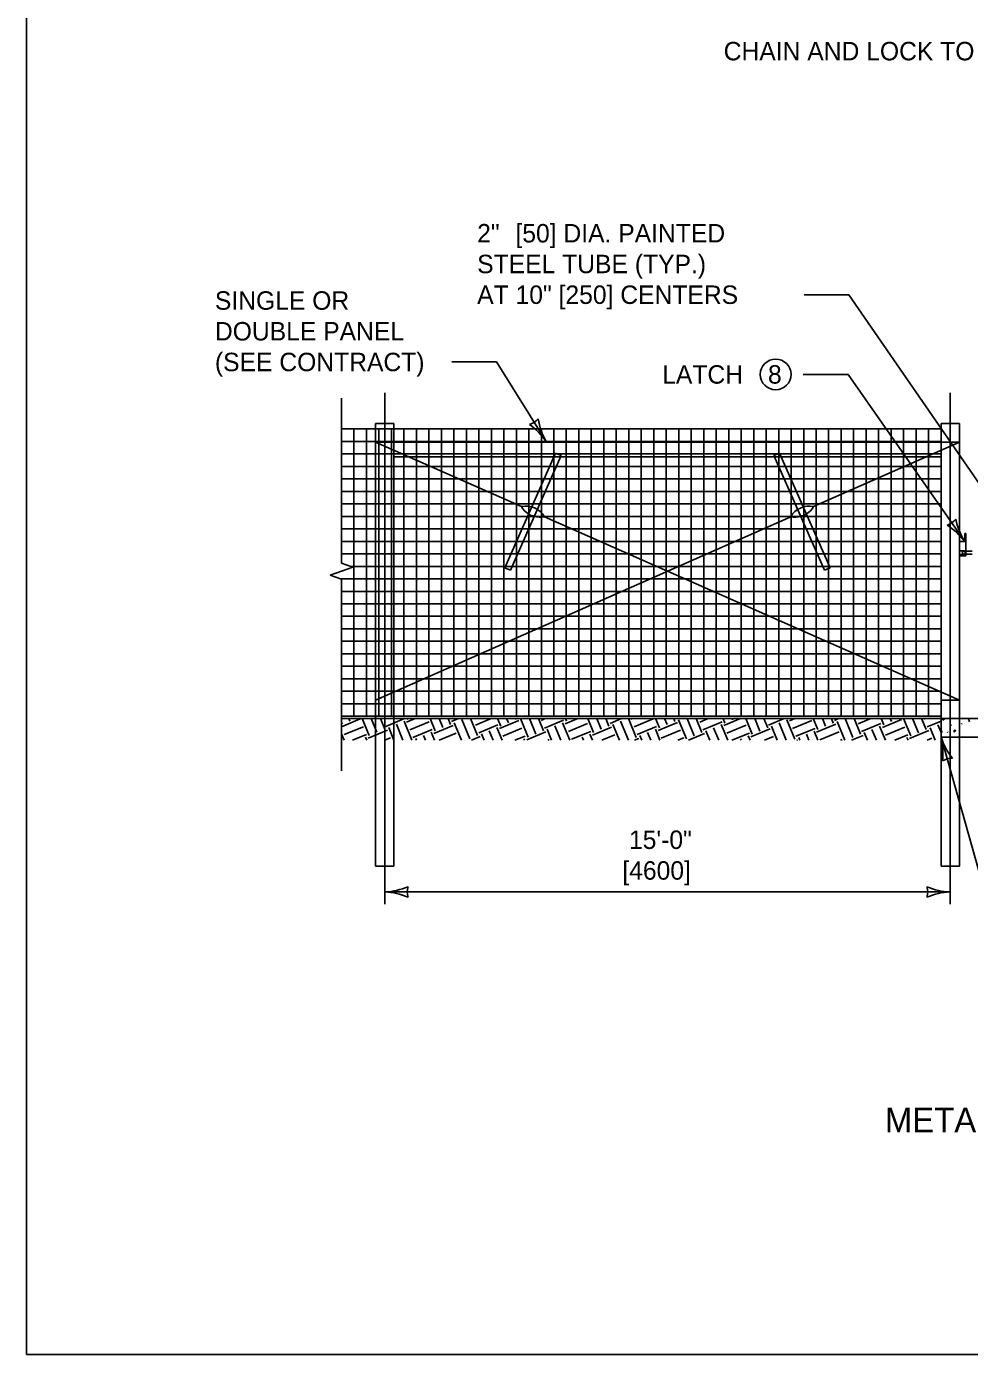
# Model space of a CAD drawing. Extents: x 49991.4 to 50021, y 49987.6 to 50011.4.
# Drawn here: x 49999.384 to 50002.451, y 49987.799 to 49992.12 of the extents above; entities that cross this region are included whole.
import ezdxf

# ---------------------------------------------------------------- set-up
doc = ezdxf.new("R2010")
doc.units = 0
for name, color, linetype in [('Level 1', 7, 'Continuous'), ('Level 2', 7, 'Continuous'), ('Level 3', 7, 'Continuous'), ('Level 4', 7, 'Continuous'), ('Level 5', 7, 'Continuous'), ('Level 6', 7, 'Continuous')]:
    doc.layers.add(name, color=color, linetype=linetype)

msp = doc.modelspace()

# ---------------------------------------------------------------- linework, layer by layer
at = {"layer": 'Level 1'}
for p, q in [((50000.5187, 49990.8278), (50000.5187, 49989.8678)), ((50000.5788, 49990.8278), (50000.5187, 49990.8278)), ((50000.5788, 49989.8678), (50000.5788, 49990.8278)), ((50002.3588, 49990.8278), (50002.3588, 49989.8078)), ((50002.4188, 49990.8278), (50002.3588, 49990.8278)), ((50002.4188, 49989.8678), (50002.4188, 49990.8278)), ((50002.3588, 49990.8105), (50000.4081, 49990.8105)), ((50000.4487, 49989.8757), (50000.4487, 49990.8105)), ((50000.4893, 49989.8757), (50000.4893, 49990.8105)), ((50000.5299, 49989.8757), (50000.5299, 49990.8105)), ((50000.5706, 49989.8757), (50000.5706, 49990.8105)), ((50000.6112, 49989.8757), (50000.6112, 49990.8105)), ((50000.6519, 49989.8757), (50000.6519, 49990.8105)), ((50000.6925, 49989.8757), (50000.6925, 49990.8105)), ((50000.7332, 49989.8757), (50000.7332, 49990.8105)), ((50000.7738, 49989.8757), (50000.7738, 49990.8105)), ((50000.8144, 49989.8757), (50000.8144, 49990.8105)), ((50000.8551, 49989.8757), (50000.8551, 49990.8105)), ((50000.8957, 49989.8757), (50000.8957, 49990.8105)), ((50000.9364, 49989.8757), (50000.9364, 49990.8105)), ((50000.977, 49989.8757), (50000.977, 49990.8105)), ((50001.0177, 49989.8757), (50001.0177, 49990.8105)), ((50001.0583, 49989.8757), (50001.0583, 49990.8105)), ((50001.0989, 49989.8757), (50001.0989, 49990.8105)), ((50001.1396, 49989.8757), (50001.1396, 49990.8105)), ((50001.1802, 49989.8757), (50001.1802, 49990.8105)), ((50001.2209, 49989.8757), (50001.2209, 49990.8105)), ((50001.2615, 49989.8757), (50001.2615, 49990.8105)), ((50001.3021, 49989.8757), (50001.3021, 49990.8105)), ((50001.3428, 49989.8757), (50001.3428, 49990.8105)), ((50001.3834, 49989.8757), (50001.3834, 49990.8105)), ((50001.4241, 49989.8757), (50001.4241, 49990.8105)), ((50001.4647, 49989.8757), (50001.4647, 49990.8105)), ((50001.5054, 49989.8757), (50001.5054, 49990.8105)), ((50001.546, 49989.8757), (50001.546, 49990.8105)), ((50001.5866, 49989.8757), (50001.5866, 49990.8105)), ((50001.6273, 49989.8757), (50001.6273, 49990.8105)), ((50001.6679, 49989.8757), (50001.6679, 49990.8105)), ((50001.7086, 49989.8757), (50001.7086, 49990.8105)), ((50001.7492, 49989.8757), (50001.7492, 49990.8105)), ((50001.7898, 49989.8757), (50001.7898, 49990.8105)), ((50001.8305, 49989.8757), (50001.8305, 49990.8105)), ((50001.8711, 49989.8757), (50001.8711, 49990.8105)), ((50001.9118, 49989.8757), (50001.9118, 49990.8105)), ((50001.9524, 49989.8757), (50001.9524, 49990.8105)), ((50001.9931, 49989.8757), (50001.9931, 49990.8105)), ((50002.0337, 49989.8757), (50002.0337, 49990.8105)), ((50002.0743, 49989.8757), (50002.0743, 49990.8105)), ((50002.115, 49989.8757), (50002.115, 49990.8105)), ((50002.1556, 49989.8757), (50002.1556, 49990.8105)), ((50002.1963, 49989.8757), (50002.1963, 49990.8105)), ((50002.2369, 49989.8757), (50002.2369, 49990.8105)), ((50002.2776, 49989.8757), (50002.2776, 49990.8105)), ((50002.3182, 49989.8757), (50002.3182, 49990.8105)), ((50002.3588, 49990.7698), (50000.4081, 49990.7698)), ((50002.3588, 49990.7292), (50000.4081, 49990.7292)), ((50000.5187, 49990.7678), (50002.4188, 49990.7678)), ((50000.5187, 49990.7678), (50000.9937, 49990.5578)), ((50000.9392, 49990.3586), (50001.1043, 49990.7321)), ((50001.1043, 49990.7321), (50001.1226, 49990.7241)), ((50001.8332, 49990.7322), (50001.8149, 49990.7241)), ((50001.9983, 49990.3586), (50001.8332, 49990.7322)), ((50002.4188, 49990.7678), (50001.9438, 49990.5577)), ((50002.3588, 49990.6885), (50000.4081, 49990.6885)), ((50000.5788, 49990.7198), (50002.3588, 49990.7198)), ((50001.1226, 49990.7241), (50000.9575, 49990.3505)), ((50001.8149, 49990.7241), (50001.98, 49990.3505)), ((50002.3588, 49990.6479), (50000.4081, 49990.6479)), ((50002.3588, 49990.6072), (50000.4081, 49990.6072)), ((50002.3588, 49990.5666), (50000.4081, 49990.5666)), ((50002.3588, 49990.526), (50000.4081, 49990.526)), ((50001.8695, 49990.5249), (50000.5187, 49989.9277)), ((50001.0681, 49990.5249), (50002.4188, 49989.9278)), ((50002.3588, 49990.4853), (50000.4081, 49990.4853)), ((50002.4363, 49990.4445), (50002.4363, 49990.4699)), ((50002.4363, 49990.4699), (50002.4389, 49990.4699)), ((50002.4389, 49990.4028), (50002.4389, 49990.4699)), ((50002.3588, 49990.4447), (50000.4081, 49990.4447)), ((50002.4189, 49990.4445), (50002.4389, 49990.4445)), ((50002.3588, 49990.404), (50000.4081, 49990.404)), ((50002.4188, 49990.414), (50002.4389, 49990.414)), ((50002.4188, 49990.4015), (50002.4389, 49990.4015)), ((50002.4188, 49990.3978), (50002.4389, 49990.3978)), ((50002.4289, 49990.4128), (50002.4289, 49990.4028)), ((50002.4289, 49990.4128), (50002.4376, 49990.4128)), ((50002.4289, 49990.4028), (50002.4376, 49990.4028)), ((50002.4376, 49990.4028), (50002.4376, 49990.414)), ((50002.4376, 49990.4028), (50002.4382, 49990.4022)), ((50002.4389, 49990.4028), (50002.4382, 49990.4022)), ((50002.4389, 49990.4128), (50002.4602, 49990.4128)), ((50002.4389, 49990.4028), (50002.4602, 49990.4028)), ((50002.4389, 49990.4015), (50002.4389, 49990.3978)), ((50002.3588, 49990.3634), (50000.4375, 49990.3634)), ((50000.9392, 49990.3586), (50000.9575, 49990.3505)), ((50001.9983, 49990.3586), (50001.98, 49990.3505)), ((50002.3588, 49990.3228), (50000.4057, 49990.3228)), ((50002.3588, 49990.2821), (50000.4081, 49990.2821)), ((50002.3588, 49990.2415), (50000.4081, 49990.2415)), ((50002.3588, 49990.2008), (50000.4081, 49990.2008)), ((50002.3588, 49990.1602), (50000.4081, 49990.1602)), ((50002.3588, 49990.1195), (50000.4081, 49990.1195)), ((50002.3588, 49990.0789), (50000.4081, 49990.0789)), ((50002.3588, 49990.0383), (50000.4081, 49990.0383)), ((50002.3588, 49989.9976), (50000.4081, 49989.9976)), ((50002.3588, 49989.957), (50000.4081, 49989.957)), ((50002.3588, 49989.9163), (50000.4081, 49989.9163)), ((50002.4188, 49989.9278), (50002.3588, 49989.9278)), ((50002.3588, 49989.8757), (50000.4081, 49989.8757)), ((50000.4081, 49989.8678), (50004.9435, 49989.8678)), ((50000.4081, 49989.8415), (50000.4689, 49989.8668)), ((50000.4324, 49989.8678), (50000.4357, 49989.8598)), ((50000.4759, 49989.8678), (50000.4986, 49989.813)), ((50000.5052, 49989.8678), (50000.5236, 49989.8234)), ((50000.5346, 49989.8678), (50000.5486, 49989.8337)), ((50000.5419, 49989.8677), (50000.5422, 49989.8678)), ((50000.5523, 49989.8426), (50000.6131, 49989.8678)), ((50000.6199, 49989.8565), (50000.6473, 49989.8678)), ((50000.6226, 49989.8678), (50000.6238, 49989.8649)), ((50000.6965, 49989.8678), (50000.7128, 49989.8284)), ((50000.7259, 49989.8678), (50000.7379, 49989.8388)), ((50000.7552, 49989.8678), (50000.7629, 49989.8491)), ((50000.7659, 49989.8582), (50000.789, 49989.8678)), ((50000.7999, 49989.8649), (50000.8258, 49989.8023)), ((50000.828, 49989.8678), (50000.8508, 49989.8127)), ((50000.8441, 49989.8466), (50000.8952, 49989.8678)), ((50000.9161, 49989.8678), (50000.926, 49989.8438)), ((50000.9454, 49989.8678), (50000.951, 49989.8542)), ((50000.9748, 49989.8678), (50000.9761, 49989.8646)), ((50000.99, 49989.8678), (50001.015, 49989.8073)), ((50001.0193, 49989.8678), (50001.0401, 49989.8177)), ((50001.0487, 49989.8678), (50001.0651, 49989.8281)), ((50001.0578, 49989.8622), (50001.0711, 49989.8678)), ((50001.136, 49989.8506), (50001.1774, 49989.8678)), ((50001.1367, 49989.8678), (50001.1403, 49989.8592)), ((50001.2095, 49989.8678), (50001.2282, 49989.8228)), ((50001.2389, 49989.8678), (50001.2532, 49989.8331)), ((50001.2682, 49989.8678), (50001.2783, 49989.8435)), ((50001.2819, 49989.8524), (50001.3191, 49989.8678)), ((50001.3421, 49989.8678), (50001.3673, 49989.807)), ((50001.3496, 49989.8662), (50001.3533, 49989.8678)), ((50001.36, 49989.8412), (50001.4226, 49989.8671)), ((50001.4302, 49989.8678), (50001.4425, 49989.8382)), ((50001.4595, 49989.8678), (50001.4675, 49989.8485)), ((50001.4889, 49989.8678), (50001.4926, 49989.8589)), ((50001.5044, 49989.8643), (50001.5304, 49989.8017)), ((50001.5324, 49989.8678), (50001.5554, 49989.8121)), ((50001.5617, 49989.8678), (50001.5805, 49989.8225)), ((50001.5738, 49989.8564), (50001.6013, 49989.8678)), ((50001.6498, 49989.8678), (50001.6556, 49989.8536)), ((50001.6518, 49989.8452), (50001.7063, 49989.8678)), ((50001.6791, 49989.8678), (50001.6807, 49989.864)), ((50001.7237, 49989.8678), (50001.7446, 49989.8171)), ((50001.753, 49989.8678), (50001.7697, 49989.8275)), ((50001.7824, 49989.8678), (50001.7947, 49989.8379)), ((50001.7978, 49989.847), (50001.848, 49989.8678)), ((50001.8567, 49989.864), (50001.8827, 49989.8014)), ((50001.8656, 49989.8604), (50001.8834, 49989.8678)), ((50001.9432, 49989.8678), (50001.9578, 49989.8326)), ((50001.9726, 49989.8678), (50001.9829, 49989.8429)), ((50002.0019, 49989.8678), (50002.0079, 49989.8533)), ((50002.0116, 49989.8622), (50002.0251, 49989.8678)), ((50002.0465, 49989.8678), (50002.0719, 49989.8064)), ((50002.0758, 49989.8678), (50002.0969, 49989.8168)), ((50002.0896, 49989.851), (50002.1302, 49989.8678)), ((50002.1639, 49989.8678), (50002.1721, 49989.8479)), ((50002.1678, 49989.8393), (50002.2304, 49989.8653)), ((50002.1932, 49989.8678), (50002.1971, 49989.8583)), ((50002.2367, 49989.8678), (50002.26, 49989.8115)), ((50002.266, 49989.8678), (50002.2851, 49989.8219)), ((50002.2954, 49989.8678), (50002.3101, 49989.8323)), ((50002.3034, 49989.8662), (50002.3073, 49989.8678)), ((50002.3588, 49989.8678), (50003.0415, 49989.8678)), ((50000.408, 49989.8557), (50000.4106, 49989.8494)), ((50000.4167, 49989.8158), (50000.4793, 49989.8417)), ((50000.4947, 49989.8046), (50000.5573, 49989.8305)), ((50000.5616, 49989.8391), (50000.5788, 49989.7976)), ((50000.5867, 49989.8495), (50000.6082, 49989.7976)), ((50000.6117, 49989.8599), (50000.6375, 49989.7976)), ((50000.6303, 49989.8314), (50000.6929, 49989.8573)), ((50000.6407, 49989.8064), (50000.7033, 49989.8323)), ((50000.6997, 49989.8234), (50000.7104, 49989.7976)), ((50000.7085, 49989.8198), (50000.7711, 49989.8457)), ((50000.7259, 49989.7976), (50000.7815, 49989.8207)), ((50000.7748, 49989.8546), (50000.7984, 49989.7976)), ((50000.8545, 49989.8216), (50000.9171, 49989.8475)), ((50000.8889, 49989.8285), (50000.9017, 49989.7976)), ((50000.9139, 49989.8388), (50000.931, 49989.7976)), ((50000.9221, 49989.8354), (50000.9848, 49989.8613)), ((50000.9325, 49989.8104), (50000.9951, 49989.8363)), ((50001.0107, 49989.7987), (50001.0733, 49989.8247)), ((50001.0681, 49989.8372), (50001.1308, 49989.8631)), ((50001.077, 49989.8335), (50001.0919, 49989.7976)), ((50001.102, 49989.8439), (50001.1212, 49989.7976)), ((50001.1271, 49989.8543), (50001.1506, 49989.7976)), ((50001.1463, 49989.8256), (50001.2089, 49989.8515)), ((50001.1567, 49989.8005), (50001.2193, 49989.8264)), ((50001.2243, 49989.8144), (50001.287, 49989.8403)), ((50001.2913, 49989.8489), (50001.3125, 49989.7976)), ((50001.3163, 49989.8593), (50001.3419, 49989.7976)), ((50001.3703, 49989.8161), (50001.433, 49989.8421)), ((50001.4042, 49989.8228), (50001.4147, 49989.7976)), ((50001.4293, 49989.8332), (50001.444, 49989.7976)), ((50001.4381, 49989.8295), (50001.5008, 49989.8555)), ((50001.4485, 49989.8045), (50001.5111, 49989.8304)), ((50001.5841, 49989.8313), (50001.6468, 49989.8573)), ((50001.5935, 49989.8279), (50001.606, 49989.7976)), ((50001.6185, 49989.8382), (50001.6353, 49989.7976)), ((50001.6436, 49989.8486), (50001.6647, 49989.7976)), ((50001.6621, 49989.8201), (50001.7248, 49989.8461)), ((50001.6786, 49989.7976), (50001.7351, 49989.821)), ((50001.7403, 49989.8085), (50001.803, 49989.8344)), ((50001.8066, 49989.8433), (50001.8256, 49989.7976)), ((50001.8317, 49989.8537), (50001.8549, 49989.7976)), ((50001.876, 49989.8353), (50001.9386, 49989.8613)), ((50001.8863, 49989.8103), (50001.949, 49989.8362)), ((50001.9458, 49989.8276), (50001.9582, 49989.7976)), ((50001.954, 49989.8241), (50002.0166, 49989.8501)), ((50001.9643, 49989.7991), (50002.027, 49989.825)), ((50002.0209, 49989.8587), (50002.0462, 49989.7976)), ((50002.1, 49989.8259), (50002.1626, 49989.8519)), ((50002.1088, 49989.8222), (50002.119, 49989.7976)), ((50002.1339, 49989.8326), (50002.1484, 49989.7976)), ((50002.1589, 49989.843), (50002.1777, 49989.7976)), ((50002.1781, 49989.8143), (50002.2408, 49989.8402)), ((50002.2562, 49989.8031), (50002.3188, 49989.829)), ((50002.3138, 49989.8411), (50002.3588, 49989.8598)), ((50002.3231, 49989.8376), (50002.3397, 49989.7976)), ((50002.3481, 49989.848), (50002.3588, 49989.8222)), ((50002.3797, 49989.8245), (50002.3806, 49989.8228)), ((50002.392, 49989.8451), (50002.3921, 49989.8472)), ((50002.4258, 49989.8495), (50002.4259, 49989.8516)), ((50000.408, 49989.8189), (50000.4169, 49989.7976)), ((50000.4437, 49989.7976), (50000.4897, 49989.8167)), ((50000.4614, 49989.7976), (50000.4614, 49989.7976)), ((50000.4865, 49989.808), (50000.4908, 49989.7976)), ((50000.5487, 49989.7976), (50000.5677, 49989.8055)), ((50000.6496, 49989.8027), (50000.6517, 49989.7976)), ((50000.6746, 49989.8131), (50000.681, 49989.7976)), ((50000.8309, 49989.7976), (50000.8595, 49989.8095)), ((50000.8638, 49989.8181), (50000.8723, 49989.7976)), ((50000.9726, 49989.7976), (50001.0055, 49989.8112)), ((50001.0018, 49989.8024), (50001.0038, 49989.7976)), ((50001.0789, 49989.7976), (50001.0837, 49989.7996)), ((50001.1911, 49989.8074), (50001.1951, 49989.7976)), ((50001.2161, 49989.8178), (50001.2245, 49989.7976)), ((50001.2548, 49989.7976), (50001.2973, 49989.8152)), ((50001.361, 49989.7976), (50001.3755, 49989.8036)), ((50001.3792, 49989.8125), (50001.3853, 49989.7976)), ((50001.5027, 49989.7976), (50001.5215, 49989.8054)), ((50001.5369, 49989.7976), (50001.5891, 49989.8192)), ((50001.7064, 49989.8018), (50001.7082, 49989.7976)), ((50001.7315, 49989.8122), (50001.7375, 49989.7976)), ((50001.7849, 49989.7976), (50001.8133, 49989.8094)), ((50001.8899, 49989.7976), (50001.8913, 49989.7982)), ((50001.8957, 49989.8068), (50001.8995, 49989.7976)), ((50001.9207, 49989.8172), (50001.9288, 49989.7976)), ((50002.0316, 49989.7976), (50002.0373, 49989.8)), ((50002.0671, 49989.7976), (50002.1052, 49989.8134)), ((50002.2088, 49989.7976), (50002.2511, 49989.8152)), ((50002.2479, 49989.8065), (50002.2516, 49989.7976)), ((50002.3138, 49989.7976), (50002.3292, 49989.804)), ((50002.3588, 49989.8078), (50003.0415, 49989.8078))]:
    msp.add_line(p, q, dxfattribs=at)
msp.add_lwpolyline([(49999.3835, 49998.9992), (50016.7501, 49998.9992), (50016.7501, 49987.7988), (49999.3835, 49987.7988)], close=True, dxfattribs=at)
for points in [[(50002.3644, 49989.8625), (50002.3647, 49989.8678)], [(50002.3676, 49989.8678), (50002.37, 49989.8672), (50002.3644, 49989.8625)], [(50002.4142, 49989.8664), (50002.4143, 49989.8678)], [(50002.4159, 49989.8678), (50002.4142, 49989.8664)], [(50002.451, 49989.8575), (50002.4484, 49989.8678)], [(50002.3588, 49989.827), (50002.3623, 49989.8255), (50002.3588, 49989.8217)], [(50002.4011, 49989.8243), (50002.4015, 49989.8303), (50002.4067, 49989.8289), (50002.4011, 49989.8243)]]:
    msp.add_lwpolyline(points, dxfattribs=at)
for centre, start, end in [((50001.0082, 49990.49), 30.2802, 101.9943), ((50001.0536, 49990.5928), 210.3068, 237.8986), ((50001.9294, 49990.4898), 78.0215, 149.6655), ((50001.8839, 49990.5927), 302.1534, 329.6769), ((50001.0537, 49990.5928), 254.439, 281.9762), ((50001.8839, 49990.5927), 258.0137, 285.561)]:
    msp.add_arc(centre, 0.0694, start, end, dxfattribs=at)
at = {"layer": 'Level 2'}
msp.add_circle((50001.8207, 49990.988), 0.05, dxfattribs=at)
at = {"layer": 'Level 3'}
for p, q in [((50002.0589, 49991.2474), (50001.9135, 49991.2474)), ((50002.5482, 49990.5392), (50002.0589, 49991.2474)), ((50000.7668, 49991.0285), (50000.9122, 49991.0285)), ((50001.0741, 49990.7698), (50000.9122, 49991.0285)), ((50002.0561, 49990.988), (50001.9107, 49990.988)), ((50002.4363, 49990.4445), (50002.0561, 49990.988)), ((50002.3588, 49989.8078), (50002.6232, 49988.8673)), ((50000.5488, 49989.3038), (50002.3888, 49989.3038))]:
    msp.add_line(p, q, dxfattribs=at)
for centre, radius, start, end in [((50001.0061, 49990.8785), 0.0548, 284.1763, 319.8987), ((50000.8829, 49990.6366), 0.233, 34.8648, 54.1146), ((50001.2672, 49990.8799), 0.2223, 189.4935, 209.677), ((50002.3628, 49990.5496), 0.0548, 287.1141, 322.8365), ((50002.6236, 49990.5644), 0.2223, 192.4313, 212.6148), ((50002.2522, 49990.3017), 0.233, 37.8026, 57.0525), ((50002.1425, 49989.7565), 0.2223, 353.155, 13.3385), ((50002.5797, 49989.8818), 0.233, 198.5263, 217.7761), ((50002.3935, 49989.6844), 0.0548, 87.8378, 123.5602), ((50000.5373, 49989.5365), 0.233, 272.8273, 292.0772), ((50000.5396, 49989.0817), 0.2223, 67.456, 87.6395), ((50000.677, 49989.3038), 0.0548, 162.1388, 197.8612), ((50002.398, 49989.5259), 0.2223, 247.456, 267.6395), ((50002.2606, 49989.3038), 0.0548, 342.1388, 17.8612), ((50002.4003, 49989.0711), 0.233, 92.8273, 112.0772)]:
    msp.add_arc(centre, radius, start, end, dxfattribs=at)
at = {"layer": 'Level 4'}
for p, q in [((50000.5187, 49989.8678), (50000.5187, 49989.3878)), ((50000.5788, 49989.3878), (50000.5788, 49989.8678)), ((50002.4188, 49989.3878), (50002.4188, 49989.8678)), ((50002.3588, 49989.8078), (50002.3588, 49989.3878)), ((50000.5187, 49989.3878), (50000.5788, 49989.3878)), ((50002.3588, 49989.3878), (50002.4188, 49989.3878))]:
    msp.add_line(p, q, dxfattribs=at)
for centre, start, end in [((50001.0537, 49990.5928), 237.8621, 254.439), ((50001.8839, 49990.5927), 285.5614, 302.1383)]:
    msp.add_arc(centre, 0.0694, start, end, dxfattribs=at)
at = {"layer": 'Level 5'}
for p, q in [((50000.5487, 49989.2638), (50000.5487, 49990.9278)), ((50002.3888, 49989.2638), (50002.3888, 49990.9278))]:
    msp.add_line(p, q, dxfattribs=at)
at = {"layer": 'Level 6'}
for p, q in [((50000.4081, 49990.9105), (50000.4081, 49990.3738)), ((50000.4446, 49990.3609), (50000.3715, 49990.3349)), ((50000.4446, 49990.3609), (50000.4081, 49990.3738)), ((50000.4081, 49990.322), (50000.3715, 49990.3349)), ((50000.4081, 49990.322), (50000.4081, 49989.6976))]:
    msp.add_line(p, q, dxfattribs=at)

# ---------------------------------------------------------------- texts
at = {"layer": 'Level 2'}
for s, height, p in [('CHAIN AND LOCK TO BE SUPPLIED BY MDT FORCES', 0.06, (50001.6516, 49992.0101)), ('2" ', 0.06, (50000.8496, 49991.4174)), ('[50] DIA. PAINTED', 0.060003, (50000.9741, 49991.4174)), ('STEEL TUBE (TYP.)', 0.060003, (50000.8496, 49991.3174)), ('SINGLE OR ', 0.06, (49999.9963, 49991.1985)), ('AT 10" [250] CENTERS', 0.060003, (50000.8496, 49991.2174)), ('DOUBLE PANEL', 0.06, (49999.9963, 49991.0985)), ('(SEE CONTRACT)', 0.06, (49999.9963, 49990.9985)), ('LATCH', 0.06, (50001.4515, 49990.958)), ('8', 0.06, (50001.7957, 49990.958)), ('15\'-0"', 0.06, (50001.3435, 49989.4438)), ('[4600]', 0.06, (50001.3218, 49989.3438)), ('METAL EQUINE GATE', 0.08, (50002.176, 49988.5216))]:
    msp.add_text(s, height=height, dxfattribs=at).set_placement(p)

doc.saveas('drawing.dxf')
